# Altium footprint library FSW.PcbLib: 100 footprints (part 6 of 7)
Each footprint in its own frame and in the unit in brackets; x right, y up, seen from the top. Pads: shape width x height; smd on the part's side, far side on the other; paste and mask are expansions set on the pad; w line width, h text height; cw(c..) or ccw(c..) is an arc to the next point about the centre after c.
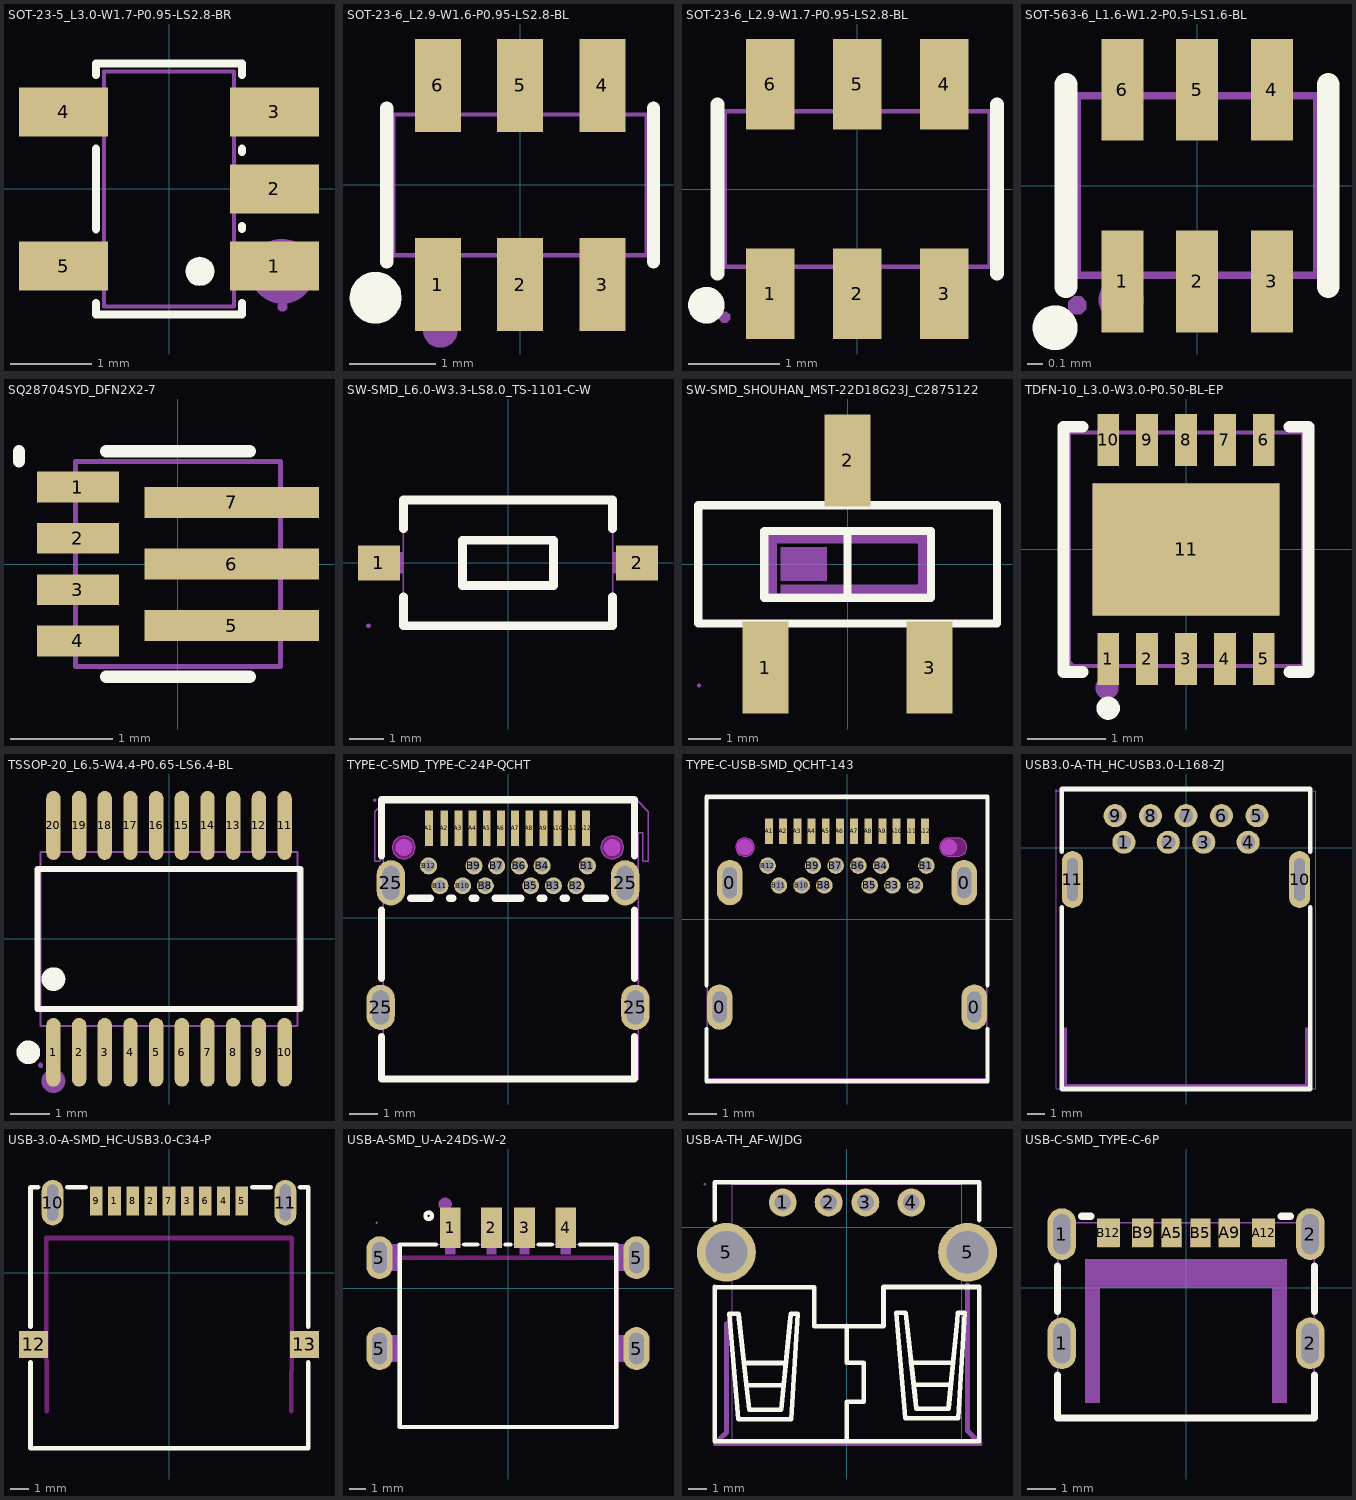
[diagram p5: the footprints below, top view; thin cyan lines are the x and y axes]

## SOT-23-5_L3.0-W1.7-P0.95-LS2.8-BR [mm]
pads (5):
  rect 1.1x0.6 smd: 1(1.3,-0.95) 2(1.3,0) 3(1.3,0.95) 4(-1.3,0.95) 5(-1.3,-0.95)
Top Overlay:
  region: 0.204,-1.016 0.212,-0.961 0.237,-0.911 0.276,-0.871 0.326,-0.846 0.381,-0.837 0.436,-0.846 0.486,-0.871 0.525,-0.911 0.55,-0.961 0.558,-1.016 0.55,-1.071 0.525,-1.121 0.486,-1.161 0.436,-1.186 0.381,-1.195 0.326,-1.186 0.276,-1.161 0.237,-1.121 0.212,-1.071 0.204,-1.016
  lines w0.1: -0.9,-1.404 -0.9,-1.55 0.9,-1.55 0.9,-1.404 ; -0.9,-0.496 -0.9,0.496 ; -0.9,1.404 -0.9,1.55 0.9,1.55 0.9,1.404 ; 0.9,-0.496 0.9,-0.454 ; 0.9,0.454 0.9,0.496
Mechanical 2:
  circle w0.4: c1.397,-1.016 r0.2
Mechanical 6:
  lines w0.051: -0.8,-1.45 -0.8,1.45 0.8,1.45 0.8,-1.45 -0.8,-1.45
Mechanical 7:
  region: -0.96,-1.15 -0.96,-0.75 -0.79,-0.75 -0.79,-1.15
  region: -0.96,0.75 -0.96,1.15 -0.79,1.15 -0.79,0.75
  region: 0.79,0.75 0.79,1.15 0.96,1.15 0.96,0.75
  region: 0.79,-0.2 0.79,0.2 0.96,0.2 0.96,-0.2
  region: 0.79,-1.15 0.79,-0.75 0.96,-0.75 0.96,-1.15
Mechanical 8:
  region: 1.46,-1.45 1.46,-1.475 1.425,-1.51 1.375,-1.51 1.34,-1.475 1.34,-1.45 1.34,-1.425 1.375,-1.39 1.425,-1.39 1.46,-1.425 1.46,-1.45
Mechanical 9:
  region: -1.4,-1.15 -1.4,-0.75 -0.95,-0.75 -0.95,-1.15
  region: -1.4,0.75 -1.4,1.15 -0.95,1.15 -0.95,0.75
  region: 0.95,0.75 0.95,1.15 1.4,1.15 1.4,0.75
  region: 0.95,-0.2 0.95,0.2 1.4,0.2 1.4,-0.2
  region: 0.95,-1.15 0.95,-0.75 1.4,-0.75 1.4,-1.15
3D body "SOT-23-5_L3.0-W1.7-P0.95-LS2.8-BL.step": height 1.2, standoff -0.05, extent -1.506,-1.45 1.506,1.45

## SOT-23-6_L2.9-W1.6-P0.95-LS2.8-BL [mm]
pads (6):
  rect 0.531x1.072 smd: 1(-0.95,-1.151) 2(0,-1.151) 3(0.95,-1.151) 4(0.95,1.148) 5(0,1.148) 6(-0.95,1.148)
Top Overlay:
  lines w0.152: -1.539,-0.889 -1.539,0.889 ; 1.539,-0.889 1.539,0.889
  lines w0.3: -1.819,-1.303 -1.808,-1.25 -1.783,-1.206 -1.742,-1.171 -1.694,-1.153 -1.643,-1.153 -1.593,-1.171 -1.554,-1.206 -1.527,-1.25 -1.519,-1.303 -1.527,-1.354 -1.554,-1.4 -1.593,-1.433 -1.643,-1.45 -1.694,-1.45 -1.742,-1.433 -1.783,-1.4 -1.808,-1.354 -1.819,-1.303
Mechanical 2:
  lines w0.201: -1.021,-1.681 -1.011,-1.638 -0.983,-1.603 -0.942,-1.582 -0.899,-1.582 -0.859,-1.603 -0.831,-1.638 -0.82,-1.681 -0.831,-1.725 -0.859,-1.758 -0.899,-1.778 -0.942,-1.778 -0.983,-1.758 -1.011,-1.725 -1.021,-1.681
Mechanical 6:
  lines w0.051: -1.463,-0.813 -1.463,0.813 1.463,0.813 1.463,-0.813 -1.463,-0.813
Mechanical 7:
  region: -1.166,0.935 -0.734,0.935 -0.734,0.803 -1.166,0.803
  region: -0.216,0.935 0.216,0.935 0.216,0.803 -0.216,0.803
  region: 0.734,0.935 1.166,0.935 1.166,0.803 0.734,0.803
  region: 0.734,-0.803 1.166,-0.803 1.166,-0.935 0.734,-0.935
  region: -0.216,-0.803 0.216,-0.803 0.216,-0.935 -0.216,-0.935
  region: -1.166,-0.803 -0.734,-0.803 -0.734,-0.935 -1.166,-0.935
Mechanical 8:
  region: -1.402,-1.4 -1.412,-1.433 -1.438,-1.455 -1.471,-1.46 -1.504,-1.445 -1.521,-1.417 -1.521,-1.384 -1.504,-1.356 -1.471,-1.341 -1.438,-1.346 -1.412,-1.369
Mechanical 9:
  region: -1.166,0.925 -0.734,0.925 -0.734,1.4 -1.166,1.4
  region: -0.216,0.925 0.216,0.925 0.216,1.4 -0.216,1.4
  region: 0.734,0.925 1.166,0.925 1.166,1.4 0.734,1.4
  region: 0.734,-0.925 1.166,-0.925 1.166,-1.4 0.734,-1.4
  region: -0.216,-0.925 0.216,-0.925 0.216,-1.4 -0.216,-1.4
  region: -1.166,-0.925 -0.734,-0.925 -0.734,-1.4 -1.166,-1.4

## SOT-23-6_L2.9-W1.7-P0.95-LS2.8-BL [mm]
pads (6):
  rect 0.532x0.99 smd: 1(-0.95,-1.145) 2(0,-1.145) 3(0.95,-1.145) 4(0.95,1.145) 5(0,1.145) 6(-0.95,1.145)
Top Overlay:
  circle w0.2: c-1.651,-1.27 r0.1
  lines w0.152: -1.526,-0.926 -1.526,0.926 ; 1.526,-0.926 1.526,0.926
Mechanical 2:
  circle w0.2: c-1.016,-1.016 r0.1
Mechanical 6:
  lines w0.051: -1.45,-0.85 1.45,-0.85 1.45,0.85 -1.45,0.85 -1.45,-0.85
Mechanical 7:
  region: -0.75,1.01 -0.75,0.84 -1.15,0.84 -1.15,1.01
  region: 0.2,1.01 0.2,0.84 -0.2,0.84 -0.2,1.01
  region: 1.15,1.01 1.15,0.84 0.75,0.84 0.75,1.01
  region: 1.15,-1.01 1.15,-0.84 0.75,-0.84 0.75,-1.01
  region: 0.2,-1.01 0.2,-0.84 -0.2,-0.84 -0.2,-1.01
  region: -0.75,-1.01 -0.75,-0.84 -1.15,-0.84 -1.15,-1.01
Mechanical 8:
  region: -1.39,-1.4 -1.39,-1.425 -1.425,-1.46 -1.475,-1.46 -1.51,-1.425 -1.51,-1.4 -1.51,-1.375 -1.475,-1.34 -1.425,-1.34 -1.39,-1.375 -1.39,-1.4
Mechanical 9:
  region: -0.75,1.4 -0.75,1 -1.15,1 -1.15,1.4
  region: 0.2,1.4 0.2,1 -0.2,1 -0.2,1.4
  region: 1.15,1.4 1.15,1 0.75,1 0.75,1.4
  region: 1.15,-1.4 1.15,-1 0.75,-1 0.75,-1.4
  region: 0.2,-1.4 0.2,-1 -0.2,-1 -0.2,-1.4
  region: -0.75,-1.4 -0.75,-1 -1.15,-1 -1.15,-1.4

## SOT-563-6_L1.6-W1.2-P0.5-LS1.6-BL [mm]
pads (6):
  rect 0.28x0.68 smd: 1(-0.5,-0.64) 2(0,-0.64) 3(0.5,-0.64) 4(0.5,0.64) 5(0,0.64) 6(-0.5,0.64)
Top Overlay:
  circle w0.15: c-0.95,-0.95 r0.075
  lines w0.152: -0.876,-0.676 -0.876,0.676 ; 0.876,-0.676 0.876,0.676
Mechanical 2:
  circle w0.15: c-0.508,-0.762 r0.075
Mechanical 6:
  lines w0.051: -0.8,-0.6 0.8,-0.6 0.8,0.6 -0.8,0.6 -0.8,-0.6
Mechanical 8:
  region: -0.74,-0.8 -0.74,-0.825 -0.775,-0.86 -0.825,-0.86 -0.86,-0.825 -0.86,-0.8 -0.86,-0.775 -0.825,-0.74 -0.775,-0.74 -0.74,-0.775 -0.74,-0.8
Mechanical 9:
  region: -0.395,0.8 -0.395,0.5 -0.605,0.5 -0.605,0.8
  region: 0.105,0.8 0.105,0.5 -0.105,0.5 -0.105,0.8
  region: 0.605,0.8 0.605,0.5 0.395,0.5 0.395,0.8
  region: 0.605,-0.8 0.605,-0.5 0.395,-0.5 0.395,-0.8
  region: 0.105,-0.8 0.105,-0.5 -0.105,-0.5 -0.105,-0.8
  region: -0.395,-0.8 -0.395,-0.5 -0.605,-0.5 -0.605,-0.8
3D body "SOT-563-6_L1.6-W1.2-P0.5-LS1.6-BL.step": height 0.56, standoff 0, extent -0.8,-0.8 0.8,0.8

## SQ28704SYD_DFN2X2-7 [mm]
pads (7):
  rect 0.8x0.3 smd: 1(-0.975,0.75) 2(-0.975,0.25) 3(-0.975,-0.25) 4(-0.975,-0.75)
  rect 1.7x0.3 smd: 5(0.525,-0.6) 6(0.525,0) 7(0.525,0.6)
Top Overlay:
  lines w0.12: -1.55,1 -1.55,1.1 ; -0.7,-1.1 0.7,-1.1 ; -0.7,1.1 0.7,1.1
Mechanical 1:
  lines w0.05: -1,-1 1,-1 1,1 -1,1 -1,-1

## SW-SMD_L6.0-W3.3-LS8.0_TS-1101-C-W [mm]
pads (2):
  rect 1.2x1 smd: 1(-3.7,0) 2(3.7,0)
Top Overlay:
  lines w0.254: -3,-0.981 -3,-1.8 3,-1.8 3,-0.981 ; -3,0.981 -3,1.8 3,1.8 3,0.981 ; -1.3,-0.65 1.3,-0.65 1.3,0.65 -1.3,0.65 -1.3,-0.65
Mechanical 6:
  lines w0.051: -3,-1.8 -3,1.8 3,1.8 3,-1.8 -3,-1.8
Mechanical 7:
  region: -3.3,-0.3 -3.3,0.3 -3,0.3 -3,-0.3
  region: 3.3,0.3 3.3,-0.3 3,-0.3 3,0.3
Mechanical 8:
  region: -3.939,-1.8 -3.939,-1.825 -3.975,-1.861 -4.025,-1.861 -4.061,-1.825 -4.061,-1.8 -4.061,-1.775 -4.025,-1.739 -3.975,-1.739 -3.939,-1.775 -3.939,-1.8 -3.94,-1.8
Mechanical 9:
  region: -4,-0.3 -4,0.3 -3.3,0.3 -3.3,-0.3
  region: 4,0.3 4,-0.3 3.3,-0.3 3.3,0.3

## SW-SMD_SHOUHAN_MST-22D18G23J_C2875122 [mm]
pads (3):
  rect 1.4x2.8 smd: 1(-2.5,-3.155) 2(0,3.155) 3(2.5,-3.155)
Top Overlay:
  lines w0.254: -2.54,-1.029 -2.54,1.003 ; -2.54,-1.029 2.54,-1.029 2.54,1.003 -2.54,1.003 ; -2.54,-1.029 -2.54,1.003 ; -2.54,-1.029 0,-1.029 0,1.003 -2.54,1.003 ; -4.55,-1.813 -4.55,1.787 4.55,1.787 4.55,-1.813 -4.55,-1.813
Mechanical 2:
  region: -2.032,0.508 -0.635,0.508 -0.635,-0.508 -2.032,-0.508
  region: -2.413,-0.889 -2.413,0.889 2.413,0.889 2.413,-0.889 -2.032,-0.889 -2.032,-0.635 2.159,-0.635 2.159,0.635 -2.159,0.635 -2.159,-0.889
Mechanical 6:
  lines w0.051: -4.525,-1.75 4.525,-1.75 4.525,1.75 -4.525,1.75 -4.525,-1.75
Mechanical 7:
  region: -0.3,1.74 -0.3,2.71 0.3,2.71 0.3,1.74
  region: 2.2,-2.71 2.2,-1.74 2.8,-1.74 2.8,-2.71
  region: -2.8,-2.71 -2.8,-1.74 -2.2,-1.74 -2.2,-2.71
Mechanical 8:
  region: -4.465,-3.7 -4.465,-3.725 -4.5,-3.76 -4.55,-3.76 -4.585,-3.725 -4.585,-3.7 -4.585,-3.675 -4.55,-3.64 -4.5,-3.64 -4.465,-3.675 -4.465,-3.7
Mechanical 9:
  region: -0.3,2.7 -0.3,3.7 0.3,3.7 0.3,2.7
  region: 2.2,-3.7 2.2,-2.7 2.8,-2.7 2.8,-3.7
  region: -2.8,-3.7 -2.8,-2.7 -2.2,-2.7 -2.2,-3.7

## TDFN-10_L3.0-W3.0-P0.50-BL-EP [mm]
pads (11):
  rect 0.28x0.665 smd: 1(-1,-1.407) 2(-0.5,-1.407) 3(0,-1.407) 4(0.5,-1.407) 5(1,-1.407) 6(1,1.407) 7(0.5,1.407) 8(0,1.407) 9(-0.5,1.407) 10(-1,1.407)
  rect 2.4x1.7 smd: 11(0,0)
Top Overlay:
  circle w0.15: c-1,-2.04 r0.075
  lines w0.152: -1.331,-1.576 -1.576,-1.576 -1.576,1.576 -1.331,1.576 ; 1.331,-1.576 1.576,-1.576 1.576,1.576 1.331,1.576
Mechanical 2:
  circle w0.15: c-1.016,-1.778 r0.075
Mechanical 6:
  lines w0.051: -1.5,-1.5 -1.5,1.5 1.5,1.5 1.5,-1.5 -1.5,-1.5
Mechanical 8:
  region: -1.44,-1.5 -1.44,-1.525 -1.475,-1.56 -1.525,-1.56 -1.56,-1.525 -1.56,-1.5 -1.56,-1.475 -1.525,-1.44 -1.475,-1.44 -1.44,-1.475 -1.44,-1.5
Mechanical 9:
  region: -1.12,-1.5 -1.12,-1.1 -0.88,-1.1 -0.88,-1.5
  region: -0.62,-1.5 -0.62,-1.1 -0.38,-1.1 -0.38,-1.5
  region: -0.12,-1.5 -0.12,-1.1 0.12,-1.1 0.12,-1.5
  region: 0.38,-1.5 0.38,-1.1 0.62,-1.1 0.62,-1.5
  region: 0.88,-1.5 0.88,-1.1 1.12,-1.1 1.12,-1.5
  region: 0.88,1.5 0.88,1.1 1.12,1.1 1.12,1.5
  region: 0.38,1.5 0.38,1.1 0.62,1.1 0.62,1.5
  region: -0.12,1.5 -0.12,1.1 0.12,1.1 0.12,1.5
  region: -0.62,1.5 -0.62,1.1 -0.38,1.1 -0.38,1.5
  region: -1.12,1.5 -1.12,1.1 -0.88,1.1 -0.88,1.5
  region: -1.2,0.85 1.2,0.85 1.2,-0.85 -1.2,-0.85
3D body "TDFN-10_L3.0-W3.0-P0.50-BL-EP.step": height 0.92, standoff 0, extent -1.5,-1.51 1.5,1.51

## TSSOP-20_L6.5-W4.4-P0.65-LS6.4-BL [mm]
pads (20):
  oval 0.364x1.742 smd: 1(-2.925,-2.871) 2(-2.275,-2.871) 3(-1.625,-2.871) 4(-0.975,-2.871) 5(-0.325,-2.871) 6(0.325,-2.871) 7(0.975,-2.871) 8(1.625,-2.871) 9(2.275,-2.871) 10(2.925,-2.871) 11(2.925,2.871) 12(2.275,2.871) 13(1.625,2.871) 14(0.975,2.871) 15(0.325,2.871) 16(-0.325,2.871) 17(-0.975,2.871) 18(-1.625,2.871) 19(-2.275,2.871) 20(-2.925,2.871)
Top Overlay:
  circle w0.3: c-3.559,-2.871 r0.15
  circle w0.3: c-2.925,-1.019 r0.15
  lines w0.152: -3.326,-1.771 3.326,-1.771 3.326,1.771 -3.326,1.771 -3.326,-1.771
Mechanical 2:
  circle w0.3: c-2.925,-3.6 r0.15
Mechanical 6:
  lines w0.051: -3.25,-2.2 3.25,-2.2 3.25,2.2 -3.25,2.2 -3.25,-2.2
Mechanical 7:
  region: 2.795,2.61 2.795,2.19 3.055,2.19 3.055,2.61
  region: 2.145,2.61 2.145,2.19 2.405,2.19 2.405,2.61
  region: 1.495,2.61 1.495,2.19 1.755,2.19 1.755,2.61
  region: 0.845,2.61 0.845,2.19 1.105,2.19 1.105,2.61
  region: 0.195,2.61 0.195,2.19 0.455,2.19 0.455,2.61
  region: -0.455,2.61 -0.455,2.19 -0.195,2.19 -0.195,2.61
  region: -1.105,2.61 -1.105,2.19 -0.845,2.19 -0.845,2.61
  region: -1.755,2.61 -1.755,2.19 -1.495,2.19 -1.495,2.61
  region: -2.405,2.61 -2.405,2.19 -2.145,2.19 -2.145,2.61
  region: -3.055,2.61 -3.055,2.19 -2.795,2.19 -2.795,2.61
  region: 2.795,-2.61 2.795,-2.19 3.055,-2.19 3.055,-2.61
  region: 2.145,-2.61 2.145,-2.19 2.405,-2.19 2.405,-2.61
  region: 1.495,-2.61 1.495,-2.19 1.755,-2.19 1.755,-2.61
  region: 0.845,-2.61 0.845,-2.19 1.105,-2.19 1.105,-2.61
  region: 0.195,-2.61 0.195,-2.19 0.455,-2.19 0.455,-2.61
  region: -0.455,-2.61 -0.455,-2.19 -0.195,-2.19 -0.195,-2.61
  region: -1.105,-2.61 -1.105,-2.19 -0.845,-2.19 -0.845,-2.61
  region: -1.755,-2.61 -1.755,-2.19 -1.495,-2.19 -1.495,-2.61
  region: -2.405,-2.61 -2.405,-2.19 -2.145,-2.19 -2.145,-2.61
  region: -3.055,-2.61 -3.055,-2.19 -2.795,-2.19 -2.795,-2.61
Mechanical 8:
  region: -3.19,-3.2 -3.19,-3.225 -3.225,-3.26 -3.275,-3.26 -3.31,-3.225 -3.31,-3.2 -3.31,-3.175 -3.275,-3.14 -3.225,-3.14 -3.19,-3.175 -3.19,-3.2
Mechanical 9:
  region: 2.795,3.2 2.795,2.6 3.055,2.6 3.055,3.2
  region: 2.145,3.2 2.145,2.6 2.405,2.6 2.405,3.2
  region: 1.495,3.2 1.495,2.6 1.755,2.6 1.755,3.2
  region: 0.845,3.2 0.845,2.6 1.105,2.6 1.105,3.2
  region: 0.195,3.2 0.195,2.6 0.455,2.6 0.455,3.2
  region: -0.455,3.2 -0.455,2.6 -0.195,2.6 -0.195,3.2
  region: -1.105,3.2 -1.105,2.6 -0.845,2.6 -0.845,3.2
  region: -1.755,3.2 -1.755,2.6 -1.495,2.6 -1.495,3.2
  region: -2.405,3.2 -2.405,2.6 -2.145,2.6 -2.145,3.2
  region: -3.055,3.2 -3.055,2.6 -2.795,2.6 -2.795,3.2
  region: 2.795,-3.2 2.795,-2.6 3.055,-2.6 3.055,-3.2
  region: 2.145,-3.2 2.145,-2.6 2.405,-2.6 2.405,-3.2
  region: 1.495,-3.2 1.495,-2.6 1.755,-2.6 1.755,-3.2
  region: 0.845,-3.2 0.845,-2.6 1.105,-2.6 1.105,-3.2
  region: 0.195,-3.2 0.195,-2.6 0.455,-2.6 0.455,-3.2
  region: -0.455,-3.2 -0.455,-2.6 -0.195,-2.6 -0.195,-3.2
  region: -1.105,-3.2 -1.105,-2.6 -0.845,-2.6 -0.845,-3.2
  region: -1.755,-3.2 -1.755,-2.6 -1.495,-2.6 -1.495,-3.2
  region: -2.405,-3.2 -2.405,-2.6 -2.145,-2.6 -2.145,-3.2
  region: -3.055,-3.2 -3.055,-2.6 -2.795,-2.6 -2.795,-3.2

## TYPE-C-SMD_TYPE-C-24P-QCHT [mm]
pads (28):
  oval 1x1.6 hole 0.6 slot 1.2 at 90 deg paste-2539.97 mask+0.05: 25(-4.49,-3.158) 25(-4.13,1.233) 25(4.13,1.233) 25(4.49,-3.158)
  rect 0.275x1.25 smd paste-100 mask+0.05: A1(-2.79,3.158) A2(-2.25,3.158) A3(-1.75,3.158) A4(-1.25,3.158) A5(-0.75,3.158) A6(-0.25,3.158) A7(0.25,3.158) A8(0.75,3.158) A9(1.25,3.158) A10(1.75,3.158) A11(2.25,3.158) A12(2.75,3.158)
  round 0.6 hole 0.4 paste-2539.97 mask+0.05: B1(2.8,1.832) B2(2.4,1.132) B3(1.6,1.133) B4(1.2,1.832) B5(0.8,1.133) B6(0.4,1.833) B7(-0.4,1.832) B8(-0.8,1.132) B9(-1.2,1.833) B10(-1.6,1.133) B11(-2.4,1.132) B12(-2.8,1.833)
Top Overlay:
  lines w0.254: -4.46,-4.188 -4.46,-5.688 4.46,-5.688 4.46,-4.188 ; -4.46,-2.127 -4.46,0.28 ; -4.46,2.185 -4.46,4.162 4.46,4.162 4.46,2.185 ; -3.44,0.691 -2.737,0.691 ; -2.063,0.691 -1.937,0.691 ; -1.263,0.691 -1.137,0.691 ; -0.463,0.691 0.463,0.691 ; 1.137,0.691 1.263,0.691 ; 1.937,0.691 2.063,0.691 ; 2.737,0.691 3.44,0.691 ; 4.46,-2.127 4.46,0.28
Top Paste:
  drawing of 28 lines, arcs and shapes, not listed
Keep-Out Layer:
  board cut-out: 4.075,2.483 4.075,2.403 4.014,2.256 3.902,2.144 3.755,2.083 3.595,2.083 3.448,2.144 3.336,2.256 3.275,2.403 3.275,2.483 3.275,2.563 3.336,2.71 3.448,2.822 3.595,2.883 3.755,2.883 3.902,2.822 4.014,2.71 4.075,2.563 4.075,2.483
  board cut-out: -3.275,2.483 -3.275,2.403 -3.336,2.256 -3.448,2.144 -3.595,2.083 -3.755,2.083 -3.902,2.144 -4.014,2.256 -4.075,2.403 -4.075,2.483 -4.075,2.563 -4.014,2.71 -3.902,2.822 -3.755,2.883 -3.595,2.883 -3.448,2.822 -3.336,2.71 -3.275,2.563 -3.275,2.483
Keep-Out Layer:
  circle w0.003: c3.675,2.483 r0.4
  circle w0.003: c-3.675,2.483 r0.4
  region: 4.075,2.483 4.065,2.394 4.035,2.309 3.988,2.234 3.924,2.17 3.849,2.123 3.764,2.093 3.675,2.083 3.586,2.093 3.501,2.123 3.426,2.17 3.362,2.234 3.315,2.309 3.285,2.394 3.275,2.483 3.285,2.572 3.315,2.657 3.362,2.732 3.426,2.796 3.501,2.843 3.586,2.873 3.675,2.883 3.764,2.873 3.849,2.843 3.924,2.796 3.988,2.732 4.035,2.657 4.065,2.572
  region: 4.075,2.483 4.075,2.403 4.014,2.256 3.902,2.144 3.755,2.083 3.595,2.083 3.448,2.144 3.336,2.256 3.275,2.403 3.275,2.483 3.275,2.563 3.336,2.71 3.448,2.822 3.595,2.883 3.755,2.883 3.902,2.822 4.014,2.71 4.075,2.563 4.075,2.483
  region: -3.275,2.483 -3.285,2.394 -3.315,2.309 -3.362,2.234 -3.426,2.17 -3.501,2.123 -3.586,2.093 -3.675,2.083 -3.764,2.093 -3.849,2.123 -3.924,2.17 -3.988,2.234 -4.035,2.309 -4.065,2.394 -4.075,2.483 -4.065,2.572 -4.035,2.657 -3.988,2.732 -3.924,2.796 -3.849,2.843 -3.764,2.873 -3.675,2.883 -3.586,2.873 -3.501,2.843 -3.426,2.796 -3.362,2.732 -3.315,2.657 -3.285,2.572
  region: -3.275,2.483 -3.275,2.403 -3.336,2.256 -3.448,2.144 -3.595,2.083 -3.755,2.083 -3.902,2.144 -4.014,2.256 -4.075,2.403 -4.075,2.483 -4.075,2.563 -4.014,2.71 -3.902,2.822 -3.755,2.883 -3.595,2.883 -3.448,2.822 -3.336,2.71 -3.275,2.563 -3.275,2.483
Mechanical 1:
  circle w0.003: c3.675,2.483 r0.4
  circle w0.003: c-3.675,2.483 r0.4
Mechanical 2:
  circle w0.3: c3.675,2.483 r0.15
  circle w0.3: c-3.675,2.483 r0.15
Mechanical 6:
  lines w0.051: -4.7,2 -4.5,2 -4.5,3 -4.4,3 -4.4,-5.7 4.6,-5.7 4.6,3 4.75,3 4.75,2 4.95,2 4.95,3.75 4.55,4.15 -4.3,4.15 -4.7,3.75 -4.7,2
Mechanical 8:
  region: -4.64,4.15 -4.64,4.125 -4.675,4.09 -4.725,4.09 -4.76,4.125 -4.76,4.15 -4.76,4.175 -4.725,4.21 -4.675,4.21 -4.64,4.175 -4.64,4.15
Mechanical 9:
  region: 3.98,1.582 4.28,1.582 4.28,0.882 3.98,0.882
  region: 2.7,1.907 2.9,1.907 2.9,1.757 2.7,1.757
  region: 2.3,1.207 2.5,1.207 2.5,1.057 2.3,1.057
  region: 1.5,1.207 1.7,1.207 1.7,1.057 1.5,1.057
  region: 1.1,1.907 1.3,1.907 1.3,1.757 1.1,1.757
  region: 0.701,1.207 0.901,1.207 0.901,1.057 0.701,1.057
  region: -2.5,1.207 -2.3,1.207 -2.3,1.057 -2.5,1.057
  region: -1.7,1.207 -1.5,1.207 -1.5,1.057 -1.7,1.057
  region: -0.9,1.207 -0.7,1.207 -0.7,1.057 -0.9,1.057
  region: -1.3,1.907 -1.1,1.907 -1.1,1.757 -1.3,1.757
  region: 0.3,1.907 0.5,1.907 0.5,1.757 0.3,1.757
  region: -0.5,1.907 -0.3,1.907 -0.3,1.757 -0.5,1.757
  region: -2.9,1.757 -2.9,1.907 -2.7,1.907 -2.7,1.757
  region: 4.34,-2.808 4.64,-2.808 4.64,-3.508 4.34,-3.508
  region: -4.64,-2.808 -4.34,-2.808 -4.34,-3.508 -4.64,-3.508
  region: -4.28,1.583 -3.98,1.583 -3.98,0.883 -4.28,0.883
  region: -2.89,3.332 -2.69,3.332 -2.69,2.682 -2.89,2.682
  region: -2.35,3.332 -2.15,3.332 -2.15,2.682 -2.35,2.682
  region: -1.85,3.332 -1.65,3.332 -1.65,2.682 -1.85,2.682
  region: -1.35,3.332 -1.15,3.332 -1.15,2.682 -1.35,2.682
  region: -0.85,3.332 -0.65,3.332 -0.65,2.682 -0.85,2.682
  region: -0.35,3.332 -0.15,3.332 -0.15,2.682 -0.35,2.682
  region: 0.15,3.332 0.35,3.332 0.35,2.682 0.15,2.682
  region: 0.65,3.332 0.85,3.332 0.85,2.682 0.65,2.682
  region: 1.15,3.332 1.35,3.332 1.35,2.682 1.15,2.682
  region: 1.65,3.332 1.85,3.332 1.85,2.682 1.65,2.682
  region: 2.15,3.332 2.35,3.332 2.35,2.682 2.15,2.682
  region: 2.65,3.332 2.85,3.332 2.85,2.682 2.65,2.682
3D body "TYPE-C-SMD_TYPE-C-24P-QCHT.step": height 2.98, standoff -1.43, extent -4.82,-5.687 4.82,4.163

## TYPE-C-USB-SMD_QCHT-143 [mm]
pads (28):
  oval 0.9x1.6 hole 0.5 slot 1.1 at 90 deg paste-2539.97 mask+0.05: 0(-4.49,-3.1) 0(-4.13,1.29) 0(4.13,1.29) 0(4.49,-3.1)
  rect 0.28x0.9 smd paste-100 mask+0.05: A1(-2.75,3.1) A2(-2.25,3.1) A3(-1.75,3.1) A4(-1.25,3.1) A5(-0.75,3.1) A6(-0.25,3.1) A7(0.25,3.1) A8(0.75,3.1) A9(1.25,3.1) A10(1.75,3.1) A11(2.25,3.1) A12(2.75,3.1)
  round 0.58 hole 0.4 paste-2539.97 mask+0.05: B1(2.8,1.89) B2(2.4,1.19) B3(1.6,1.19) B4(1.2,1.89) B5(0.8,1.19) B6(0.4,1.89) B7(-0.4,1.89) B8(-0.8,1.19) B9(-1.2,1.89) B10(-1.6,1.19) B11(-2.4,1.19) B12(-2.8,1.89)
Top Overlay:
  lines w0.15: -4.953,-3.875 -4.953,-5.715 4.953,-5.715 4.953,-3.875 ; -4.953,-2.325 -4.953,4.318 4.953,4.318 4.953,-2.325
Top Paste:
  drawing of 28 lines, arcs and shapes, not listed
Keep-Out Layer:
  board cut-out: 3.899,2.866 3.971,2.857 4.04,2.833 4.101,2.795 4.153,2.743 4.192,2.681 4.216,2.613 4.224,2.54 4.216,2.468 4.192,2.399 4.153,2.338 4.102,2.286 4.04,2.248 3.972,2.224 3.899,2.216 3.599,2.216 3.526,2.224 3.458,2.248 3.396,2.286 3.345,2.338 3.306,2.399 3.282,2.468 3.274,2.54 3.274,2.541 3.282,2.613 3.306,2.682 3.345,2.743 3.396,2.795 3.457,2.833 3.526,2.857 3.598,2.866 3.599,2.866 3.899,2.866
  board cut-out: -3.275,2.54 -3.275,2.475 -3.324,2.356 -3.416,2.264 -3.535,2.215 -3.665,2.215 -3.784,2.264 -3.875,2.356 -3.925,2.475 -3.925,2.54 -3.925,2.605 -3.875,2.724 -3.784,2.815 -3.665,2.865 -3.535,2.865 -3.416,2.815 -3.324,2.724 -3.275,2.605 -3.275,2.54
Keep-Out Layer:
  circle w0.003: c-3.6,2.54 r0.325
  region: 3.899,2.866 3.971,2.857 4.04,2.833 4.101,2.795 4.153,2.743 4.192,2.681 4.216,2.613 4.224,2.54 4.216,2.468 4.192,2.399 4.153,2.338 4.102,2.286 4.04,2.248 3.972,2.224 3.899,2.216 3.599,2.216 3.526,2.224 3.458,2.248 3.396,2.286 3.345,2.338 3.306,2.399 3.282,2.468 3.274,2.54 3.274,2.541 3.282,2.613 3.306,2.682 3.345,2.743 3.396,2.795 3.457,2.833 3.526,2.857 3.598,2.866 3.599,2.866 3.899,2.866
  region: 3.899,2.866 3.971,2.857 4.04,2.833 4.101,2.795 4.153,2.743 4.192,2.681 4.216,2.613 4.224,2.54 4.216,2.468 4.192,2.399 4.153,2.338 4.102,2.286 4.04,2.248 3.972,2.224 3.899,2.216 3.599,2.216 3.526,2.224 3.458,2.248 3.396,2.286 3.345,2.338 3.306,2.399 3.282,2.468 3.274,2.54 3.274,2.541 3.282,2.613 3.306,2.682 3.345,2.743 3.396,2.795 3.457,2.833 3.526,2.857 3.598,2.866 3.599,2.866 3.899,2.866
  region: -3.275,2.54 -3.275,2.475 -3.324,2.356 -3.416,2.264 -3.535,2.215 -3.665,2.215 -3.784,2.264 -3.875,2.356 -3.925,2.475 -3.925,2.54 -3.925,2.605 -3.875,2.724 -3.784,2.815 -3.665,2.865 -3.535,2.865 -3.416,2.815 -3.324,2.724 -3.275,2.605 -3.275,2.54
  region: -3.275,2.54 -3.284,2.462 -3.312,2.389 -3.357,2.324 -3.415,2.272 -3.485,2.236 -3.561,2.217 -3.639,2.217 -3.715,2.236 -3.785,2.272 -3.843,2.324 -3.888,2.389 -3.915,2.462 -3.925,2.54 -3.915,2.618 -3.888,2.691 -3.843,2.755 -3.785,2.807 -3.715,2.844 -3.639,2.862 -3.561,2.862 -3.485,2.844 -3.415,2.807 -3.357,2.755 -3.312,2.691 -3.284,2.618
  lines w0.003: 3.899,2.216 ccw(c3.899,2.54) 4.224,2.54 ; 3.899,2.216 3.899,2.216 ; 3.899,2.216 3.599,2.216 cw(c3.599,2.54) 3.274,2.54 3.274,2.541 cw(c3.598,2.541) 3.598,2.866 3.599,2.866 3.899,2.866 cw(c3.899,2.54) 4.224,2.54 ; 4.224,2.54 4.224,2.54
Mechanical 1:
  circle w0.003: c-3.6,2.54 r0.325
  lines w0.003: 3.899,2.216 ccw(c3.899,2.54) 4.224,2.54 ; 3.899,2.216 3.899,2.216 ; 3.899,2.216 3.599,2.216 cw(c3.599,2.54) 3.274,2.54 3.274,2.541 cw(c3.598,2.541) 3.598,2.866 3.599,2.866 3.899,2.866 cw(c3.899,2.54) 4.224,2.54 ; 4.224,2.54 4.224,2.54
Mechanical 2:
  circle w0.28: c-3.6,2.54 r0.14
  circle w0.28: c3.6,2.54 r0.14
Mechanical 6:
  lines w0.051: -4.925,-5.63 -4.925,4.24 4.925,4.24 4.925,-5.63 -4.925,-5.63
Mechanical 8:
  region: -4.865,4.24 -4.865,4.215 -4.9,4.18 -4.95,4.18 -4.985,4.215 -4.985,4.24 -4.985,4.265 -4.95,4.3 -4.9,4.3 -4.865,4.265 -4.865,4.24
Mechanical 9:
  region: -2.85,3.425 -2.65,3.425 -2.65,2.775 -2.85,2.775
  region: -2.35,3.425 -2.15,3.425 -2.15,2.775 -2.35,2.775
  region: -1.85,3.425 -1.65,3.425 -1.65,2.775 -1.85,2.775
  region: -1.35,3.425 -1.15,3.425 -1.15,2.775 -1.35,2.775
  region: -0.85,3.425 -0.65,3.425 -0.65,2.775 -0.85,2.775
  region: -0.35,3.425 -0.15,3.425 -0.15,2.775 -0.35,2.775
  region: 0.15,3.425 0.35,3.425 0.35,2.775 0.15,2.775
  region: 0.65,3.425 0.85,3.425 0.85,2.775 0.65,2.775
  region: 1.15,3.425 1.35,3.425 1.35,2.775 1.15,2.775
  region: 1.65,3.425 1.85,3.425 1.85,2.775 1.65,2.775
  region: 2.15,3.425 2.35,3.425 2.35,2.775 2.15,2.775
  region: 2.65,3.425 2.85,3.425 2.85,2.775 2.65,2.775
  region: 2.675,2.015 2.925,2.015 2.925,1.765 2.675,1.765
  region: 2.275,1.315 2.525,1.315 2.525,1.065 2.275,1.065
  region: 1.475,1.315 1.725,1.315 1.725,1.065 1.475,1.065
  region: 1.075,2.015 1.325,2.015 1.325,1.765 1.075,1.765
  region: 0.675,1.315 0.925,1.315 0.925,1.065 0.675,1.065
  region: 0.275,2.015 0.525,2.015 0.525,1.765 0.275,1.765
  region: -0.525,2.015 -0.275,2.015 -0.275,1.765 -0.525,1.765
  region: -0.925,1.315 -0.675,1.315 -0.675,1.065 -0.925,1.065
  region: -1.325,2.015 -1.075,2.015 -1.075,1.765 -1.325,1.765
  region: -1.725,1.315 -1.475,1.315 -1.475,1.065 -1.725,1.065
  region: -2.525,1.315 -2.275,1.315 -2.275,1.065 -2.525,1.065
  region: -2.925,2.015 -2.675,2.015 -2.675,1.765 -2.925,1.765
  region: -4.255,1.69 -4.005,1.69 -4.005,0.89 -4.255,0.89
  region: 4.005,1.69 4.255,1.69 4.255,0.89 4.005,0.89
  region: -4.615,-2.7 -4.365,-2.7 -4.365,-3.5 -4.615,-3.5
  region: 4.365,-2.7 4.615,-2.7 4.615,-3.5 4.365,-3.5

## USB3.0-A-TH_HC-USB3.0-L168-ZJ [mm]
pads (11):
  round 1.3 hole 0.8: 1(-3.5,0.3) 2(-1,0.3) 3(1,0.3) 4(3.5,0.3) 5(4,1.8) 6(2,1.8) 7(0,1.8) 8(-2,1.8) 9(-4,1.8)
  oval 1.2x3.2 hole 0.6 slot 2.415 at 90 deg: 10(6.4,-1.8) 11(-6.4,-1.8)
Top Overlay:
  lines w0.254: -7,-3.374 -7,-13.6 7,-13.6 7,-3.374 ; -7,-0.226 -7,3.302 7,3.302 ; 7,-0.226 7,3.175
Mechanical 2:
  region: -6.985,-10.16 -6.985,-13.589 6.985,-13.589 6.985,-10.16 6.731,-10.16 6.731,-13.335 -6.731,-13.335 -6.731,-10.16
Mechanical 6:
  lines w0.051: -7.3,-13.6 7.3,-13.6 7.3,3.2 -7.3,3.2 -7.3,-13.6
Mechanical 8:
  region: -7.24,3.2 -7.24,3.175 -7.275,3.14 -7.325,3.14 -7.36,3.175 -7.36,3.2 -7.36,3.225 -7.325,3.26 -7.275,3.26 -7.24,3.225 -7.24,3.2
Mechanical 9:
  region: -6.55,-0.85 -6.25,-0.85 -6.25,-2.75 -6.55,-2.75
  region: 6.25,-0.85 6.55,-0.85 6.55,-2.75 6.25,-2.75
  region: -4.3,1.95 -3.7,1.95 -3.7,1.65 -4.3,1.65
  region: -2.3,1.95 -1.7,1.95 -1.7,1.65 -2.3,1.65
  region: -0.3,1.95 0.3,1.95 0.3,1.65 -0.3,1.65
  region: 1.7,1.95 2.3,1.95 2.3,1.65 1.7,1.65
  region: 3.7,1.95 4.3,1.95 4.3,1.65 3.7,1.65
  region: 3.2,0.45 3.8,0.45 3.8,0.15 3.2,0.15
  region: 0.7,0.45 1.3,0.45 1.3,0.15 0.7,0.15
  region: -1.3,0.45 -0.7,0.45 -0.7,0.15 -1.3,0.15
  region: -3.8,0.45 -3.2,0.45 -3.2,0.15 -3.8,0.15
3D body "USB3.0-A-TH_HC-USB3.0-L168-ZJ.step": height 7.65, standoff -2.95, extent -7.2,-13.48 7.2,3.32

## USB-3.0-A-SMD_HC-USB3.0-C34-P [mm]
pads (13):
  rect 0.7x1.6 smd paste+0 mask+0.051: 1(-3,3.95) 2(-1,3.95) 3(1,3.95) 4(3,3.95) 5(4,3.95) 6(2,3.95) 7(0,3.95) 8(-2,3.95) 9(-4,3.95)
  oval 1.2x2.5 hole 0.6 slot 2 at 90 deg paste-2539.97 mask+0.051: 10(-6.4,3.85) 11(6.4,3.85)
  rect 1.6x1.5 smd paste+0 mask+0.051: 12(-7.45,-3.95) 13(7.45,-3.95)
Top Overlay:
  lines w0.254: -7.62,-4.931 -7.62,-9.652 7.659,-9.652 7.659,-4.931 ; -7.62,-2.969 -7.62,2.54 -7.62,4.699 -7.207,4.699 ; -5.593,4.699 -4.581,4.699 ; 4.581,4.699 5.593,4.699 ; 7.207,4.699 7.659,4.699 7.659,-2.969
Keep-Out Layer:
  lines w0.254: -6.75,-4.826 -6.75,-3.048 -6.75,1.905 6.75,1.905 6.75,-3.175 6.731,-7.62 ; -6.731,-7.62 -6.731,-4.826

## USB-A-SMD_U-A-24DS-W-2 [mm]
pads (8):
  rect 1.25x2.45 smd paste-100 mask+0.051: 1(-3.5,3.663) 2(-1,3.663) 3(1,3.663) 4(3.5,3.663)
  oval 1.6x2.6 hole 0.9 slot 1.9 at 90 deg: 5(-7.775,-3.662) 5(-7.775,1.838) 5(7.775,-3.662) 5(7.775,1.838)
Top Overlay:
  circle w0.254: c-4.8,4.37 r0.2
  lines w0.254: -4.356,2.642 -6.55,2.642 -6.55,-8.408 6.55,-8.408 6.55,2.583 ; -2.644,2.642 -1.856,2.642 ; -0.144,2.642 0.144,2.642 ; 1.856,2.642 2.644,2.642 ; 4.356,2.642 6.55,2.642
Top Paste:
  drawing of 8 lines, arcs and shapes, not listed
Keep-Out Layer:
  lines w0.254: -6.6,-8.373 -6.6,1.838 6.6,1.838 6.6,-8.365
Mechanical 2:
  circle w0.4: c-3.8,5.07 r0.2
Mechanical 6:
  lines w0.051: -6.55,-8.408 -6.55,2.642 6.55,2.642 6.55,-8.408 -6.55,-8.408
Mechanical 7:
  region: -6.453,1.04 -7.953,1.04 -7.953,2.64 -6.453,2.64
  region: -6.453,-4.46 -7.953,-4.46 -7.953,-2.86 -6.453,-2.86
  region: 7.953,-4.46 6.453,-4.46 6.453,-2.86 7.953,-2.86
  region: 7.953,1.04 6.453,1.04 6.453,2.64 7.953,2.64
Mechanical 8:
  region: -7.894,3.942 -7.894,3.917 -7.929,3.882 -7.978,3.882 -8.013,3.917 -8.013,3.942 -8.013,3.967 -7.978,4.002 -7.929,4.002 -7.894,3.967 -7.894,3.942
Mechanical 9:
  region: -7.95,2.638 -7.6,2.638 -7.6,1.038 -7.95,1.038
  region: 7.6,2.638 7.95,2.638 7.95,1.038 7.6,1.038
  region: -7.95,-2.863 -7.6,-2.863 -7.6,-4.463 -7.95,-4.463
  region: 7.6,-2.863 7.95,-2.863 7.95,-4.463 7.6,-4.463
  region: -3.8,3.942 -3.2,3.942 -3.2,2.042 -3.8,2.042
  region: -1.3,3.942 -0.7,3.942 -0.7,2.042 -1.3,2.042
  region: 0.7,3.942 1.3,3.942 1.3,2.042 0.7,2.042
  region: 3.2,3.942 3.8,3.942 3.8,2.042 3.2,2.042
3D body "USB-A-SMD_U-A-24DS-Y-1.step": height 6.9, standoff -2.4, extent 10.668,-7.471 24.968,3.429

## USB-A-TH_AF-WJDG [mm]
pads (6):
  round 1.52 hole 0.92 paste-2539.97 mask+0.05: 1(-3.5,1.355) 2(-1,1.355) 3(1,1.355) 4(3.5,1.355)
  round 3.2 hole 2.3 paste-2539.97 mask+0.05: 5(-6.57,-1.355) 5(6.57,-1.355)
Top Overlay:
  lines w0.254: -7.199,-3.236 -7.199,-11.655 7.201,-11.655 7.201,-3.236 ; -7.199,0.404 -7.199,2.46 7.201,2.46 7.201,0.404 ; -7.19,-3.266 -1.79,-3.266 -1.79,-5.385 1.99,-5.385 1.99,-3.245 7.19,-3.245 ; -5.609,-7.385 -3.349,-7.385 ; -5.469,-8.595 -3.439,-8.595 ; -0.01,-11.525 -0.01,-9.495 0.91,-9.495 0.91,-7.376 -0.01,-7.376 -0.01,-5.355 ; 3.49,-7.366 5.75,-7.366 ; 3.63,-8.576 5.66,-8.576 ; -6.42,-4.706 -5.911,-4.71 -5.401,-9.25 -5.325,-9.928 -3.576,-9.917 -3.102,-5.139 -3.072,-4.709 -2.691,-4.709 -3.041,-10.452 -5.925,-10.441 -6.42,-4.706 ; 2.682,-4.652 3.19,-4.656 3.701,-9.196 3.776,-9.874 5.526,-9.864 6,-5.085 6.03,-4.655 6.41,-4.655 6.06,-10.398 3.177,-10.387 2.682,-4.652
Mechanical 2:
  region: -6.443,-5.27 -6.443,-11.17 -6.453,-11.219 -6.48,-11.26 -6.863,-11.643 6.943,-11.643 6.47,-11.17 6.443,-11.129 6.433,-11.08 6.433,-3.14 6.443,-3.091 6.47,-3.05 6.511,-3.023 6.56,-3.013 6.609,-3.023 6.65,-3.05 6.677,-3.091 6.687,-3.14 6.687,-11.027 7.34,-11.68 7.367,-11.721 7.377,-11.77 7.367,-11.819 7.34,-11.86 7.299,-11.887 7.25,-11.897 -7.17,-11.897 -7.219,-11.887 -7.26,-11.86 -7.287,-11.819 -7.297,-11.77 -7.287,-11.721 -7.26,-11.68 -6.697,-11.117 -6.697,-5.27 -6.687,-5.221 -6.66,-5.18 -6.619,-5.153 -6.57,-5.143 -6.521,-5.153 -6.48,-5.18 -6.453,-5.221
Mechanical 6:
  lines w0.051: -6.25,-11.655 6.25,-11.655 6.25,2.345 -6.25,2.345 -6.25,-11.655
Mechanical 7:
  region: -6.24,-2.105 -7.75,-2.105 -7.75,-0.605 -6.24,-0.605
  region: 6.24,-0.605 7.75,-0.605 7.75,-2.105 6.24,-2.105
Mechanical 8:
  region: -7.69,2.345 -7.69,2.32 -7.725,2.285 -7.775,2.285 -7.81,2.32 -7.81,2.345 -7.81,2.37 -7.775,2.405 -7.725,2.405 -7.69,2.37 -7.69,2.345
Mechanical 9:
  region: -6.82,-0.605 -6.32,-0.605 -6.32,-2.105 -6.82,-2.105
  region: 6.32,-0.605 6.82,-0.605 6.82,-2.105 6.32,-2.105
  region: 3.2,1.205 3.2,1.505 3.8,1.505 3.8,1.205
  region: 0.7,1.205 0.7,1.505 1.3,1.505 1.3,1.205
  region: -1.3,1.205 -1.3,1.505 -0.7,1.505 -0.7,1.205
  region: -3.8,1.205 -3.8,1.505 -3.2,1.505 -3.2,1.205
3D body "USB-A-TH_AF-WJDG.step": height 7.64, standoff -3.87, extent -7.753,-12.08 7.747,1.92

## USB-C-SMD_TYPE-C-6P [mm]
pads (10):
  oval 1x1.8 hole 0.6 slot 1.4 at 90 deg paste-2539.97 mask+0.05: 1(-4.32,-1.925) 1(-4.32,1.875) 2(4.32,-1.925) 2(4.32,1.875)
  rect 0.7x1 smd paste-100 mask+0.05: A5(-0.499,1.925) B5(0.501,1.925)
  rect 0.75x1 smd paste-100 mask+0.05: A9(1.501,1.925) B9(-1.499,1.925)
  rect 0.8x1 smd paste-100 mask+0.05: A12(2.701,1.925) B12(-2.699,1.925)
Top Overlay:
  lines w0.254: -4.47,-3.04 -4.47,-4.525 4.47,-4.525 4.47,-3.04 ; -4.47,-0.809 -4.47,0.76 ; -3.625,2.5 -3.318,2.5 ; 3.32,2.5 3.625,2.5 ; 4.47,-0.809 4.47,0.76
Top Paste:
  drawing of 10 lines, arcs and shapes, not listed
Mechanical 2:
  region: -3,1 3,1 3,0 -3,0
  region: 3.5,-4 3,-4 3,1 3.5,1
  region: -3.5,-4 -3.5,1 -3,1 -3,-4
Mechanical 6:
  lines w0.051: -4.47,-4.525 4.47,-4.525 4.47,2.275 -4.47,2.275 -4.47,-4.525
Mechanical 8:
  region: -4.41,-4.525 -4.41,-4.55 -4.445,-4.585 -4.495,-4.585 -4.53,-4.55 -4.53,-4.525 -4.53,-4.5 -4.495,-4.465 -4.445,-4.465 -4.41,-4.5 -4.41,-4.525
Mechanical 9:
  region: 2.351,2.125 3.051,2.125 3.051,1.425 2.351,1.425
  region: 1.151,2.125 1.851,2.125 1.851,1.425 1.151,1.425
  region: 0.151,2.125 0.851,2.125 0.851,1.425 0.151,1.425
  region: -0.849,2.125 -0.149,2.125 -0.149,1.425 -0.849,1.425
  region: -1.849,2.125 -1.149,2.125 -1.149,1.425 -1.849,1.425
  region: -3.049,2.125 -2.349,2.125 -2.349,1.425 -3.049,1.425
  region: 4.17,2.275 4.47,2.275 4.47,1.475 4.17,1.475
  region: 4.17,-1.525 4.47,-1.525 4.47,-2.325 4.17,-2.325
  region: -4.47,-1.525 -4.17,-1.525 -4.17,-2.325 -4.47,-2.325
  region: -4.47,2.275 -4.17,2.275 -4.17,1.475 -4.47,1.475
3D body "USB-C-SMD_TYPE-C-6P.step": height 3.36, standoff -0.75, extent -4.47,-4.445 4.47,2.355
